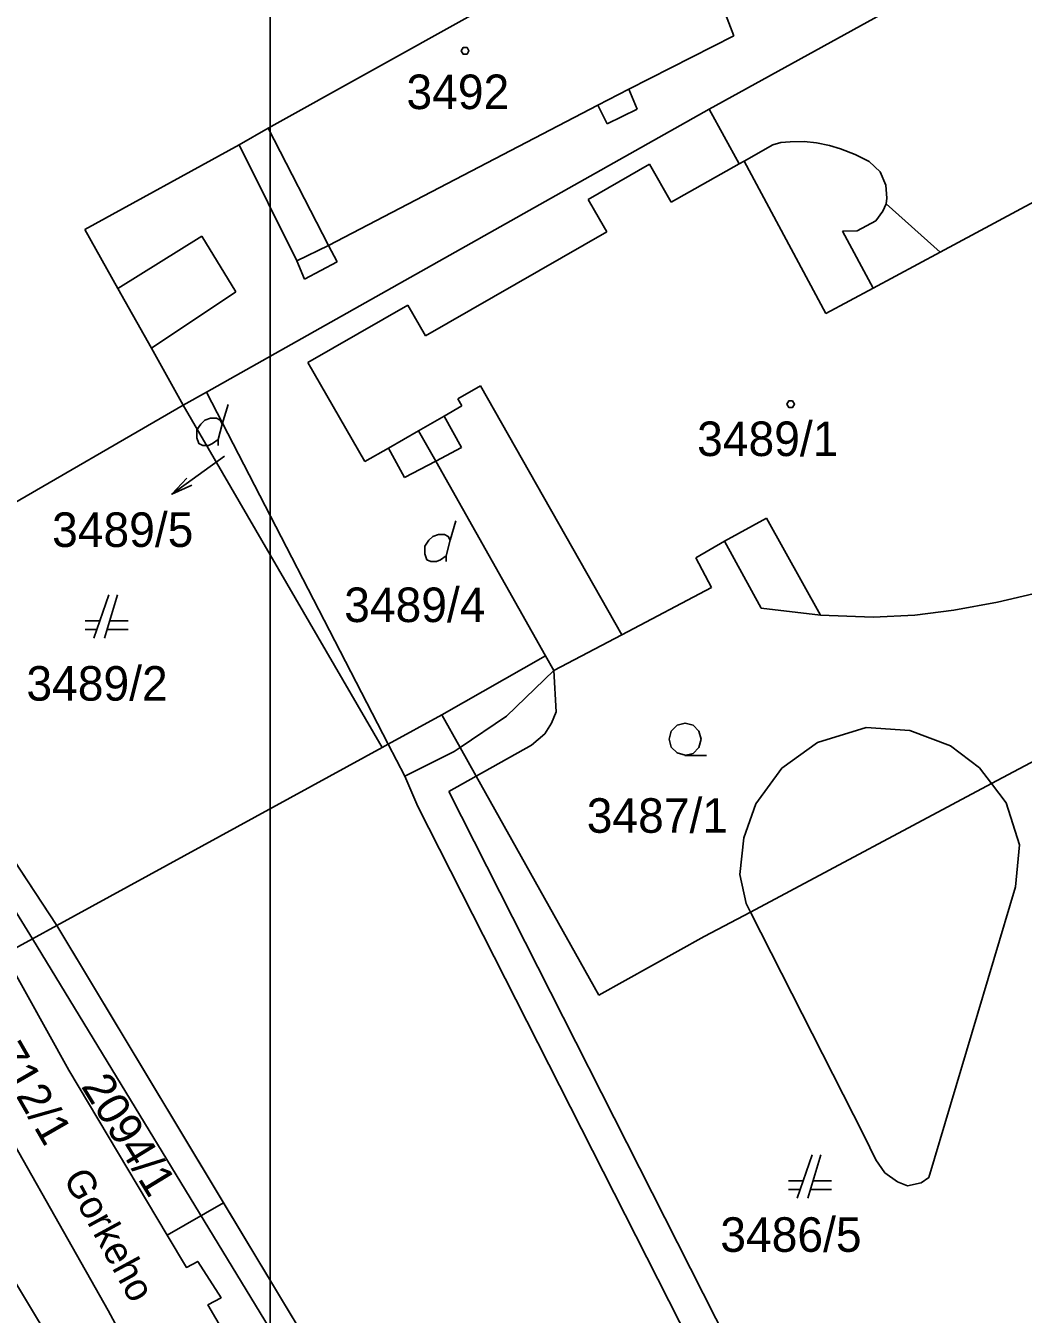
# Model space of a CAD drawing. Extents: x -263587 to -261993, y -1238795 to -1236748.
# Drawn here: x -263003.3 to -262957.1, y -1238374.1 to -1238314.4 of the extents above; entities that cross this region are included whole.
import ezdxf

# ---------------------------------------------------------------- set-up
doc = ezdxf.new("R2010")
doc.units = 0
for name, color, linetype in [('Vrstva 1', 7, 'Continuous'), ('Vrstva 3', 7, 'Continuous'), ('Vrstva 51', 7, 'Continuous')]:
    doc.layers.add(name, color=color, linetype=linetype)

msp = doc.modelspace()

# ---------------------------------------------------------------- linework, layer by layer
at = {"layer": 'Vrstva 1'}
for p, q in [((-262951.96, -1238307.39), (-262971.7, -1238318.29)), ((-262971.7, -1238318.29), (-262951.96, -1238307.39)), ((-262970.55, -1238314.89), (-262971.7, -1238311.86)), ((-262992.12, -1238319.17), (-262982.74, -1238313.95)), ((-262982.74, -1238313.95), (-262992.12, -1238319.17)), ((-262975.42, -1238317.36), (-262970.55, -1238314.89)), ((-262976.85, -1238318.1), (-262975.42, -1238317.36)), ((-262975.42, -1238317.36), (-262975.03, -1238318.28)), ((-262971.7, -1238318.29), (-262994.98, -1238331.39)), ((-262994.98, -1238331.39), (-262971.7, -1238318.29)), ((-262989.32, -1238324.6), (-262976.85, -1238318.1)), ((-262976.42, -1238318.96), (-262976.85, -1238318.1)), ((-262975.03, -1238318.28), (-262976.42, -1238318.96)), ((-262971.7, -1238318.29), (-262970.3, -1238320.82)), ((-262970.3, -1238320.82), (-262971.7, -1238318.29)), ((-262993.47, -1238319.94), (-262992.12, -1238319.17)), ((-262992.12, -1238319.17), (-262993.47, -1238319.94)), ((-262992.12, -1238319.17), (-262989.32, -1238324.6)), ((-262968.37, -1238319.82), (-262967.94, -1238319.79)), ((-262967.94, -1238319.79), (-262968.37, -1238319.82)), ((-262967.94, -1238319.79), (-262967.3, -1238319.78)), ((-262967.3, -1238319.78), (-262967.94, -1238319.79)), ((-262967.3, -1238319.78), (-262966.72, -1238319.84)), ((-262966.72, -1238319.84), (-262967.3, -1238319.78)), ((-263000.62, -1238323.85), (-262993.47, -1238319.94)), ((-262993.47, -1238319.94), (-263000.62, -1238323.85)), ((-262993.47, -1238319.94), (-262990.8, -1238325.31)), ((-262970.07, -1238320.69), (-262968.75, -1238319.94)), ((-262968.75, -1238319.94), (-262970.07, -1238320.69)), ((-262968.75, -1238319.94), (-262968.37, -1238319.82)), ((-262968.37, -1238319.82), (-262968.75, -1238319.94)), ((-262966.72, -1238319.84), (-262966.12, -1238319.96)), ((-262966.12, -1238319.96), (-262966.72, -1238319.84)), ((-262966.12, -1238319.96), (-262965.61, -1238320.12)), ((-262965.61, -1238320.12), (-262966.12, -1238319.96)), ((-262965.61, -1238320.12), (-262964.93, -1238320.38)), ((-262964.93, -1238320.38), (-262965.61, -1238320.12)), ((-262964.93, -1238320.38), (-262964.28, -1238320.71)), ((-262964.28, -1238320.71), (-262964.93, -1238320.38)), ((-262977.3, -1238322.46), (-262974.46, -1238320.83)), ((-262974.46, -1238320.83), (-262977.3, -1238322.46)), ((-262974.46, -1238320.83), (-262973.45, -1238322.59)), ((-262973.45, -1238322.59), (-262974.46, -1238320.83)), ((-262973.45, -1238322.59), (-262970.3, -1238320.82)), ((-262970.3, -1238320.82), (-262973.45, -1238322.59)), ((-262970.3, -1238320.82), (-262970.07, -1238320.69)), ((-262970.07, -1238320.69), (-262970.3, -1238320.82)), ((-262970.07, -1238320.69), (-262966.29, -1238327.74)), ((-262964.28, -1238320.71), (-262963.77, -1238321.19)), ((-262963.77, -1238321.19), (-262964.28, -1238320.71)), ((-262963.77, -1238321.19), (-262963.51, -1238321.8)), ((-262963.51, -1238321.8), (-262963.77, -1238321.19)), ((-262961, -1238324.9), (-262954.7, -1238321.52)), ((-262954.7, -1238321.52), (-262961, -1238324.9)), ((-262963.51, -1238321.8), (-262963.47, -1238322.4)), ((-262963.47, -1238322.4), (-262963.51, -1238321.8)), ((-262976.78, -1238323.38), (-262977.3, -1238322.46)), ((-262977.3, -1238322.46), (-262976.78, -1238323.38)), ((-262963.65, -1238323.01), (-262963.5, -1238322.66)), ((-262963.47, -1238322.4), (-262963.5, -1238322.66)), ((-262963.5, -1238322.66), (-262963.47, -1238322.4)), ((-262963.5, -1238322.66), (-262961, -1238324.9)), ((-262961, -1238324.9), (-262963.5, -1238322.66)), ((-262976.44, -1238323.96), (-262976.78, -1238323.38)), ((-262976.78, -1238323.38), (-262976.44, -1238323.96)), ((-262963.98, -1238323.46), (-262963.65, -1238323.01)), ((-262999.09, -1238326.59), (-263000.62, -1238323.85)), ((-263000.62, -1238323.85), (-262999.09, -1238326.59)), ((-262984.84, -1238328.78), (-262976.44, -1238323.96)), ((-262976.44, -1238323.96), (-262984.84, -1238328.78)), ((-262965.51, -1238323.93), (-262964.83, -1238323.92)), ((-262964.1, -1238326.57), (-262965.51, -1238323.93)), ((-262964.83, -1238323.92), (-262963.98, -1238323.46)), ((-262999.09, -1238326.59), (-262995.2, -1238324.16)), ((-262995.2, -1238324.16), (-262993.62, -1238326.75)), ((-262990.8, -1238325.31), (-262989.32, -1238324.6)), ((-262989.32, -1238324.6), (-262988.93, -1238325.35)), ((-262961, -1238324.9), (-262964.1, -1238326.57)), ((-262990.44, -1238326.15), (-262990.8, -1238325.31)), ((-262988.93, -1238325.35), (-262990.44, -1238326.15)), ((-262997.53, -1238329.35), (-262999.09, -1238326.59)), ((-262999.09, -1238326.59), (-262997.53, -1238329.35)), ((-262993.62, -1238326.75), (-262997.53, -1238329.35)), ((-262966.29, -1238327.74), (-262964.1, -1238326.57)), ((-262990.28, -1238330.01), (-262985.65, -1238327.36)), ((-262985.65, -1238327.36), (-262990.28, -1238330.01)), ((-262985.65, -1238327.36), (-262984.84, -1238328.78)), ((-262984.84, -1238328.78), (-262985.65, -1238327.36)), ((-262996.06, -1238332), (-262997.53, -1238329.35)), ((-262997.53, -1238329.35), (-262996.06, -1238332)), ((-262987.64, -1238334.61), (-262990.28, -1238330.01)), ((-262990.28, -1238330.01), (-262987.64, -1238334.61)), ((-262982.28, -1238331.1), (-262983.34, -1238331.7)), ((-262975.74, -1238342.63), (-262982.28, -1238331.1)), ((-262994.98, -1238331.39), (-262996.06, -1238332)), ((-262996.06, -1238332), (-262994.98, -1238331.39)), ((-262994.98, -1238331.39), (-262986.56, -1238347.69)), ((-262986.56, -1238347.69), (-262994.98, -1238331.39)), ((-262983.34, -1238331.7), (-262983.15, -1238332.03)), ((-263011.78, -1238341.08), (-262996.06, -1238332)), ((-262996.06, -1238332), (-263011.78, -1238341.08)), ((-262996.06, -1238332), (-262986.84, -1238347.85)), ((-262986.84, -1238347.85), (-262996.06, -1238332)), ((-262994.25, -1238332.87), (-262993.98, -1238331.97)), ((-262983.15, -1238332.03), (-262983.97, -1238332.51)), ((-262985.15, -1238333.18), (-262983.97, -1238332.51)), ((-262983.97, -1238332.51), (-262983.16, -1238333.95)), ((-262986.54, -1238333.98), (-262985.15, -1238333.18)), ((-262984.36, -1238334.59), (-262985.15, -1238333.18)), ((-262986.54, -1238333.98), (-262987.64, -1238334.61)), ((-262987.64, -1238334.61), (-262986.54, -1238333.98)), ((-262985.8, -1238335.35), (-262986.54, -1238333.98)), ((-262986.54, -1238333.98), (-262985.8, -1238335.35)), ((-262983.16, -1238333.95), (-262984.36, -1238334.59)), ((-262984.36, -1238334.59), (-262985.8, -1238335.35)), ((-262985.8, -1238335.35), (-262984.36, -1238334.59)), ((-262979.27, -1238343.6), (-262984.36, -1238334.59)), ((-262984.36, -1238334.59), (-262979.27, -1238343.6)), ((-262995.651, -1238335.697), (-262996.577, -1238336.123)), ((-262983.69, -1238338.25), (-262983.42, -1238337.35)), ((-262969.03, -1238337.22), (-262970.99, -1238338.3)), ((-262966.54, -1238341.72), (-262969.03, -1238337.22)), ((-262970.99, -1238338.3), (-262972.31, -1238339.06)), ((-262972.31, -1238339.06), (-262970.99, -1238338.3)), ((-262969.28, -1238341.39), (-262970.99, -1238338.3)), ((-262970.99, -1238338.3), (-262969.28, -1238341.39)), ((-262972.31, -1238339.06), (-262971.58, -1238340.44)), ((-262971.58, -1238340.44), (-262972.31, -1238339.06)), ((-262971.58, -1238340.44), (-262975.74, -1238342.63)), ((-262975.74, -1238342.63), (-262971.58, -1238340.44)), ((-263001.91, -1238356.1), (-263011.78, -1238341.08)), ((-263011.78, -1238341.08), (-263001.91, -1238356.1)), ((-262999.5, -1238340.78), (-263000.2, -1238342.78)), ((-262999.7, -1238342.78), (-262999.1, -1238340.78)), ((-262958.33, -1238341.12), (-262960.36, -1238341.49)), ((-262960.36, -1238341.49), (-262958.33, -1238341.12)), ((-262956.68, -1238340.73), (-262958.33, -1238341.12)), ((-262958.33, -1238341.12), (-262956.68, -1238340.73)), ((-263003.03, -1238356.71), (-263012.31, -1238341.74)), ((-262966.54, -1238341.72), (-262969.28, -1238341.39)), ((-262969.28, -1238341.39), (-262966.54, -1238341.72)), ((-262964.09, -1238341.81), (-262966.54, -1238341.72)), ((-262966.54, -1238341.72), (-262964.09, -1238341.81)), ((-262962.16, -1238341.72), (-262964.09, -1238341.81)), ((-262964.09, -1238341.81), (-262962.16, -1238341.72)), ((-262960.36, -1238341.49), (-262962.16, -1238341.72)), ((-262962.16, -1238341.72), (-262960.36, -1238341.49)), ((-262999.92, -1238341.98), (-263000.6, -1238341.98)), ((-263000.6, -1238342.38), (-263000.06, -1238342.38)), ((-262999.58, -1238342.38), (-262998.6, -1238342.38)), ((-262998.6, -1238341.98), (-262999.46, -1238341.98)), ((-262975.74, -1238342.63), (-262978.89, -1238344.29)), ((-262978.89, -1238344.29), (-262975.74, -1238342.63)), ((-262984.08, -1238346.33), (-262979.27, -1238343.6)), ((-262979.27, -1238343.6), (-262984.08, -1238346.33)), ((-262978.89, -1238344.29), (-262979.27, -1238343.6)), ((-262979.27, -1238343.6), (-262978.89, -1238344.29)), ((-262981.08, -1238346.4), (-262978.89, -1238344.29)), ((-262978.78, -1238346.19), (-262978.89, -1238344.29)), ((-262986.56, -1238347.69), (-262984.08, -1238346.33)), ((-262984.08, -1238346.33), (-262986.56, -1238347.69)), ((-262984.08, -1238346.33), (-262983.23, -1238347.85)), ((-262983.23, -1238347.85), (-262984.08, -1238346.33)), ((-262983.23, -1238347.85), (-262981.08, -1238346.4)), ((-262978.99, -1238346.73), (-262978.78, -1238346.19)), ((-262958.62, -1238349.52), (-262953.19, -1238346.63)), ((-262953.19, -1238346.63), (-262958.62, -1238349.52)), ((-262979.93, -1238347.74), (-262979.3, -1238347.21)), ((-262979.3, -1238347.21), (-262978.99, -1238346.73)), ((-262966.68, -1238347.62), (-262964.42, -1238346.93)), ((-262964.42, -1238346.93), (-262962.4, -1238347.06)), ((-262962.4, -1238347.06), (-262960.52, -1238347.78)), ((-262986.84, -1238347.85), (-263001.91, -1238356.1)), ((-263001.91, -1238356.1), (-262986.84, -1238347.85)), ((-262986.56, -1238347.69), (-262986.84, -1238347.85)), ((-262986.84, -1238347.85), (-262986.56, -1238347.69)), ((-262985.79, -1238349.18), (-262986.56, -1238347.69)), ((-262986.56, -1238347.69), (-262985.79, -1238349.18)), ((-262983.23, -1238347.85), (-262983.5, -1238348.03)), ((-262983.23, -1238347.85), (-262982.48, -1238349.18)), ((-262982.48, -1238349.18), (-262983.23, -1238347.85)), ((-262982.48, -1238349.18), (-262979.93, -1238347.74)), ((-262968.33, -1238348.8), (-262966.68, -1238347.62)), ((-262960.52, -1238347.78), (-262959.17, -1238348.79)), ((-262983.5, -1238348.03), (-262985.79, -1238349.18)), ((-262969.53, -1238350.46), (-262968.33, -1238348.8)), ((-262959.17, -1238348.79), (-262958.62, -1238349.52)), ((-262985.19, -1238350.59), (-262985.79, -1238349.18)), ((-262985.79, -1238349.18), (-262985.19, -1238350.59)), ((-262983.75, -1238349.89), (-262982.48, -1238349.18)), ((-262982.48, -1238349.18), (-262976.8, -1238359.32)), ((-262976.8, -1238359.32), (-262982.48, -1238349.18)), ((-262969.78, -1238355.47), (-262958.62, -1238349.52)), ((-262958.62, -1238349.52), (-262969.78, -1238355.47)), ((-262958.62, -1238349.52), (-262957.94, -1238350.42)), ((-262966.63, -1238383.67), (-262983.75, -1238349.89)), ((-262968, -1238384.43), (-262985.19, -1238350.59)), ((-262985.19, -1238350.59), (-262968, -1238384.43)), ((-262970.09, -1238352.04), (-262969.53, -1238350.46)), ((-262957.94, -1238350.42), (-262957.32, -1238352.36)), ((-262970.27, -1238353.73), (-262970.09, -1238352.04)), ((-262957.32, -1238352.36), (-262957.5, -1238354.31)), ((-262969.98, -1238355.08), (-262970.27, -1238353.73)), ((-262957.5, -1238354.31), (-262961.52, -1238367.76)), ((-262971.93, -1238356.61), (-262969.78, -1238355.47)), ((-262969.78, -1238355.47), (-262971.93, -1238356.61)), ((-262969.78, -1238355.47), (-262969.98, -1238355.08)), ((-262964.53, -1238365.81), (-262969.78, -1238355.47)), ((-263003.03, -1238356.71), (-263001.91, -1238356.1)), ((-263001.91, -1238356.1), (-262980.46, -1238391.76)), ((-262980.46, -1238391.76), (-263001.91, -1238356.1)), ((-262988.12, -1238381.22), (-263003.03, -1238356.71)), ((-262976.8, -1238359.32), (-262971.93, -1238356.61)), ((-262971.93, -1238356.61), (-262976.8, -1238359.32)), ((-263012.35, -1238358.52), (-262981.74, -1238409.23)), ((-262963.98, -1238366.95), (-262964.53, -1238365.81)), ((-262966.92, -1238366.72), (-262967.62, -1238368.72)), ((-262967.12, -1238368.72), (-262966.52, -1238366.72)), ((-262963.55, -1238367.55), (-262963.98, -1238366.95)), ((-262962.97, -1238367.97), (-262963.55, -1238367.55)), ((-262967.34, -1238367.92), (-262968.02, -1238367.92)), ((-262966.02, -1238367.92), (-262966.88, -1238367.92)), ((-262962.5, -1238368.15), (-262962.97, -1238367.97)), ((-262961.88, -1238368.02), (-262962.5, -1238368.15)), ((-262961.52, -1238367.76), (-262961.88, -1238368.02)), ((-262968.02, -1238368.32), (-262967.48, -1238368.32)), ((-262967, -1238368.32), (-262966.02, -1238368.32))]:
    msp.add_line(p, q, dxfattribs=at)
for points in [[(-262982.91, -1238315.43), (-262982.82, -1238315.58), (-262982.91, -1238315.73), (-262983.09, -1238315.73), (-262983.18, -1238315.58), (-262983.09, -1238315.43)], [(-262967.83, -1238331.8), (-262967.74, -1238331.95), (-262967.83, -1238332.1), (-262968.01, -1238332.1), (-262968.1, -1238331.95), (-262968.01, -1238331.8)]]:
    msp.add_lwpolyline(points, close=True, dxfattribs=at)
for points in [[(-262994.43, -1238333.86), (-262994.43, -1238333.59), (-262994.25, -1238332.87), (-262994.34, -1238332.69), (-262994.52, -1238332.6), (-262994.79, -1238332.6), (-262995.06, -1238332.69), (-262995.24, -1238332.87), (-262995.42, -1238333.14), (-262995.42, -1238333.5), (-262995.33, -1238333.77), (-262995.15, -1238333.86), (-262994.88, -1238333.86), (-262994.7, -1238333.77), (-262994.43, -1238333.59)], [(-262994.15, -1238334.36), (-262996.577, -1238336.123), (-262995.886, -1238335.374)], [(-262983.87, -1238339.24), (-262983.87, -1238338.97), (-262983.69, -1238338.25), (-262983.78, -1238338.07), (-262983.96, -1238337.98), (-262984.23, -1238337.98), (-262984.5, -1238338.07), (-262984.68, -1238338.25), (-262984.86, -1238338.52), (-262984.86, -1238338.88), (-262984.77, -1238339.15), (-262984.59, -1238339.24), (-262984.32, -1238339.24), (-262984.14, -1238339.15), (-262983.87, -1238338.97)], [(-262972.8, -1238348.2), (-262973.18, -1238348.1), (-262973.45, -1238347.83), (-262973.55, -1238347.46), (-262973.45, -1238347.09), (-262973.18, -1238346.82), (-262972.81, -1238346.72), (-262972.44, -1238346.82), (-262972.17, -1238347.09), (-262972.07, -1238347.47), (-262972.17, -1238347.85), (-262972.44, -1238348.12), (-262972.82, -1238348.22), (-262971.82, -1238348.22)]]:
    msp.add_lwpolyline(points, dxfattribs=at)
at = {"layer": 'Vrstva 3'}
for points in [[(-263001.91, -1238356.1), (-263003.03, -1238356.71), (-263004.33, -1238357.42), (-263013, -1238341.78), (-263011.78, -1238341.08)], [(-262994.187, -1238368.939), (-262996.8, -1238370.43), (-263001.36, -1238362.79), (-263004.33, -1238357.42), (-263003.03, -1238356.71), (-263001.91, -1238356.1)], [(-262986.735, -1238381.327), (-262989.53, -1238382.87), (-262994.91, -1238373.67), (-262994.3, -1238373.34), (-262995.38, -1238371.65), (-262995.91, -1238371.93), (-262996.8, -1238370.43), (-262994.187, -1238368.939)]]:
    msp.add_lwpolyline(points, close=True, dxfattribs=at)
for points in [[(-263004.33, -1238357.42), (-263001.36, -1238362.79), (-262996.8, -1238370.43), (-262995.91, -1238371.93), (-262995.38, -1238371.65), (-262994.3, -1238373.34), (-262994.91, -1238373.67), (-262989.53, -1238382.87)], [(-263005.95, -1238362.6), (-262999.53, -1238373.93), (-262998.59, -1238375.67)], [(-262998.59, -1238375.67), (-262999.53, -1238373.93), (-263005.95, -1238362.6)]]:
    msp.add_lwpolyline(points, dxfattribs=at)
at = {"layer": 'Vrstva 51'}
msp.add_lwpolyline([(-262992.03, -1237088.09), (-262695.03, -1237088.09), (-262695.03, -1238768.09), (-262992.03, -1238768.09)], close=True, dxfattribs=at)

# ---------------------------------------------------------------- texts
at = {"layer": 'Vrstva 1'}
for s, p in [('3492', (-262985.714, -1238318.28)), ('3489/1', (-262972.25, -1238334.35)), ('3489/5', (-263002.129, -1238338.56)), ('3489/4', (-262988.599, -1238342.04)), ('3489/2', (-263003.319, -1238345.68)), ('3487/1', (-262977.364, -1238351.8)), ('3486/5', (-262971.177, -1238371.21))]:
    msp.add_text(s, height=1.6, dxfattribs=at).set_placement(p)
msp.add_text('Gorkeho', height=1.3, rotation=298.51101, dxfattribs=at).set_placement((-263001.637, -1238367.79))
at = {"layer": 'Vrstva 3'}
for s, rotation, p in [('2712/1', 299.94341, (-263005.505, -1238361.072)), ('2094/1', 301.49039, (-263000.811, -1238363.539))]:
    msp.add_text(s, height=1.5, rotation=rotation, dxfattribs=at).set_placement(p)

doc.saveas('drawing.dxf')
